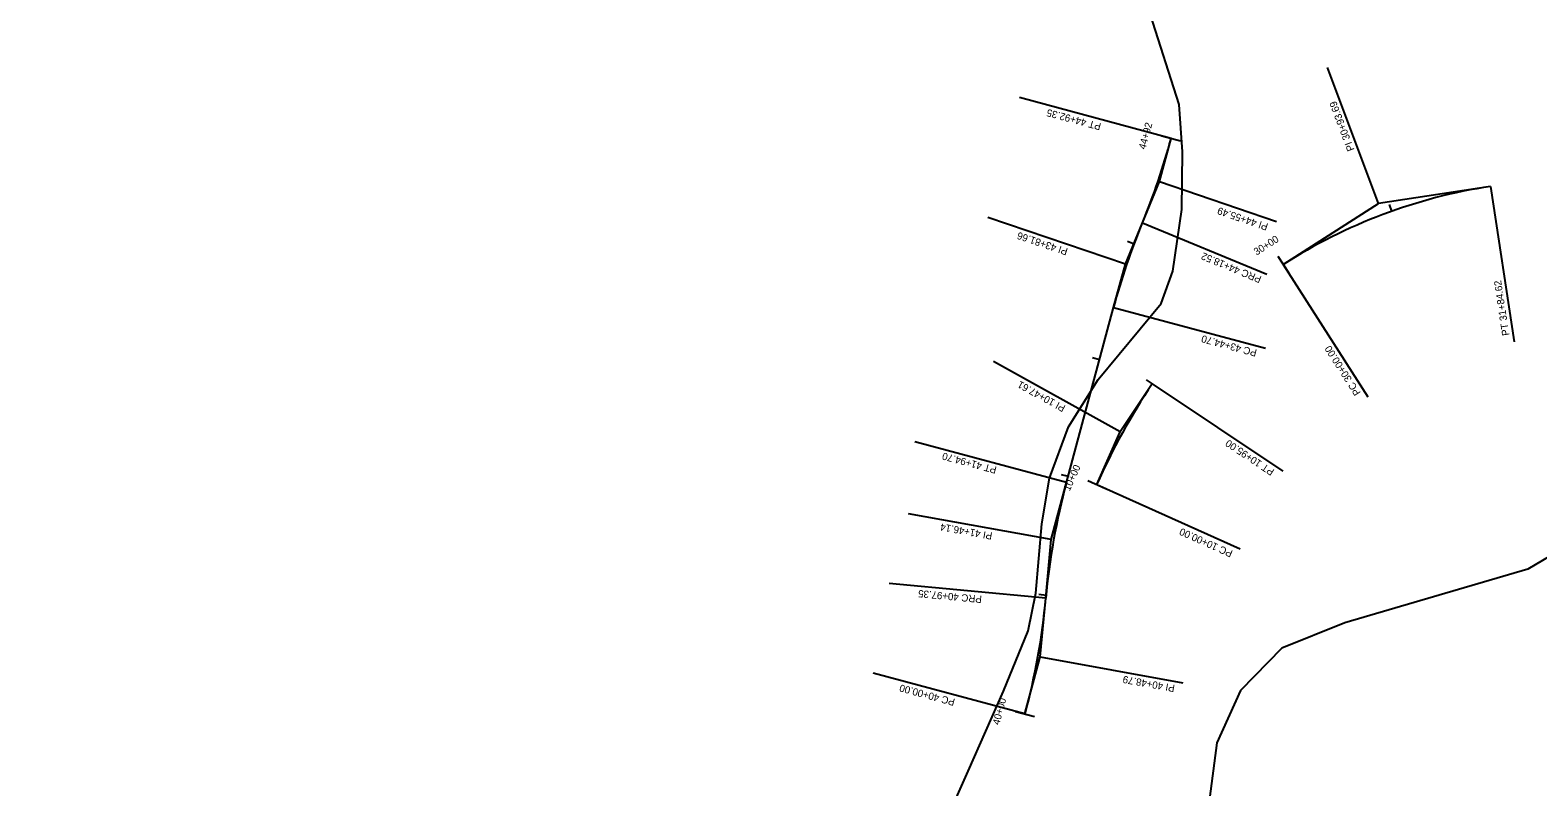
# Model space of a CAD drawing. Extents: x 983486 to 994833, y 1835619 to 1844358.
# Drawn here: x 991785 to 993032, y 1840151 to 1840776 of the extents above; entities that cross this region are included whole.
import ezdxf

# ---------------------------------------------------------------- set-up
doc = ezdxf.new("R2010")
doc.units = 0
for name, color, linetype in [('43', 7, 'Continuous'), ('R_Horz Alg', 7, 'Continuous'), ('R_Horz Alg Annot', 7, 'Continuous'), ('R_Horz Alg Stationing', 7, 'Continuous')]:
    doc.layers.add(name, color=color, linetype=linetype)

msp = doc.modelspace()

# ---------------------------------------------------------------- linework, layer by layer
at = {"layer": '43'}
for points in [[(992621.8, 1840368.1), (992628.1, 1840405.8), (992643.7, 1840448.4), (992668.3, 1840487.4), (992720.4, 1840550.2), (992730.1, 1840577), (992737.5, 1840627.9), (992738, 1840675.6), (992735.4, 1840714.9), (992711.3, 1840789.8), (992657.1, 1840913.4), (992616, 1840968.7), (992554.4, 1841054), (992492.5, 1841112.9), (992422.7, 1841167.6), (992343.9, 1841218.5), (992195, 1841300.3), (992123, 1841334.7), (992016.5, 1841376), (991968.2, 1841403.4), (991911.1, 1841449.2), (991869, 1841500.6), (991810.1, 1841556.1), (991749.1, 1841600.9)], [(992534.5, 1840104.7), (992560.8, 1840163.5), (992590.1, 1840229.7), (992610.3, 1840279.7), (992616.6, 1840310.7), (992621.8, 1840368.1)], [(993078.4, 1840362.9), (993023.9, 1840330.6), (992872.5, 1840286.1), (992820.4, 1840265.3), (992786, 1840230.3), (992766.6, 1840187.1), (992757.7, 1840119.8)]]:
    msp.add_lwpolyline(points, dxfattribs=at)
at = {"layer": 'R_Horz Alg'}
msp.add_line((992642.2, 1840402.3), (992681.1, 1840547.1), dxfattribs=at)
for centre, radius, start, end in [((992175.3, 1840835.7), 573, 337.5525, 344.9354), ((993059.1, 1840211.4), 440.7, 98.6296, 122.6308), ((993234.4, 1840398.2), 573, 157.5525, 164.9354), ((993189.9, 1840166.2), 573, 146.335, 155.835), ((993195.4, 1840253.3), 573, 164.9354, 174.6702), ((992054.5, 1840359.8), 573, 344.9354, 354.6702)]:
    msp.add_arc(centre, radius, start, end, dxfattribs=at)
at = {"layer": 'R_Horz Alg Annot'}
for p, q in [((992719, 1840651.1), (992728.6, 1840686.8)), ((992704.9, 1840617), (992719, 1840651.1)), ((992992.9, 1840647.1), (992900.3, 1840633.1)), ((992821.4, 1840582.6), (992900.3, 1840633.1)), ((992690.8, 1840582.8), (992704.9, 1840617)), ((992681.1, 1840547.1), (992690.8, 1840582.8)), ((992713, 1840483.8), (992686.6, 1840444.1)), ((992667.1, 1840400.7), (992686.6, 1840444.1)), ((992629.5, 1840355.1), (992642.2, 1840402.3)), ((992624.9, 1840306.6), (992629.5, 1840355.1)), ((992620.4, 1840258), (992624.9, 1840306.6)), ((992607.7, 1840210.9), (992620.4, 1840258))]:
    msp.add_line(p, q, dxfattribs=at)
for points in [[(992900.3, 1840633.1), (992858, 1840745.4)], [(992728.6, 1840686.8), (992603.1, 1840720.6)], [(992719, 1840651.1), (992815.9, 1840618.2)], [(992992.9, 1840647.1), (993012.4, 1840518.6)], [(992690.8, 1840582.8), (992577.1, 1840621.4)], [(992704.9, 1840617), (992807.9, 1840574.4)], [(992821.4, 1840582.6), (992891.5, 1840473.1)], [(992681.1, 1840547.1), (992806.7, 1840513.3)], [(992686.6, 1840444.1), (992581.6, 1840502.2)], [(992713, 1840483.8), (992821.2, 1840411.7)], [(992642.2, 1840402.3), (992516.6, 1840436)], [(992667.1, 1840400.7), (992785.7, 1840347.5)], [(992629.5, 1840355.1), (992511.4, 1840376.4)], [(992624.9, 1840306.6), (992495.5, 1840318.6)], [(992620.4, 1840258), (992738.5, 1840236.7)], [(992607.7, 1840210.9), (992482.2, 1840244.7)]]:
    msp.add_lwpolyline(points, dxfattribs=at)
at = {"layer": 'R_Horz Alg Stationing'}
for points in [[(992720.9, 1840688.9), (992736.3, 1840684.7)], [(992720.9, 1840688.9), (992736.3, 1840684.7)], [(992909, 1840632.2), (992911, 1840626.5)], [(992692.5, 1840601.8), (992698.1, 1840599.7)], [(992817.1, 1840589.3), (992825.7, 1840575.8)], [(992663.7, 1840505.5), (992669.5, 1840503.9)], [(992708, 1840487.1), (992713, 1840483.8)], [(992637.7, 1840408.9), (992643.5, 1840407.4)], [(992659.8, 1840404), (992674.4, 1840397.4)], [(992619.2, 1840309.8), (992625.2, 1840309.2)], [(992600, 1840212.9), (992615.5, 1840208.8)]]:
    msp.add_lwpolyline(points, dxfattribs=at)

# ---------------------------------------------------------------- texts
at = {"layer": 'R_Horz Alg Annot'}
for s, rotation, p in [('PI 30+93.69', 110.6302, (992880.4, 1840677.5)), ('PT 44+92.35', 164.9354, (992671.2, 1840699.2)), ('PI 44+55.49', 161.244, (992809.4, 1840616.1)), ('PI 43+81.66', 161.244, (992643.7, 1840595.6)), ('PRC 44+18.52', 157.5525, (992804, 1840572.5)), ('PT 31+84.62', 98.6296, (993008.6, 1840524.1)), ('PC 43+44.70', 164.9354, (992800.1, 1840512)), ('PC 30+00.00', 122.6308, (992885.8, 1840476.5)), ('PI 10+47.61', 151.085, (992641.8, 1840465.5)), ('PT 10+95.00', 146.335, (992814.6, 1840412.5)), ('PT 41+94.70', 164.9354, (992584.8, 1840415.2)), ('PI 41+46.14', 169.8028, (992581.1, 1840360.8)), ('PC 10+00.00', 155.835, (992780.2, 1840345.6)), ('PRC 40+97.35', 174.6702, (992572.3, 1840308.5)), ('PI 40+48.79', 169.8028, (992732.1, 1840234.8)), ('PC 40+00.00', 164.9354, (992550.3, 1840223.2))]:
    msp.add_text(s, height=6, rotation=rotation, dxfattribs=at).set_placement(p)
at = {"layer": 'R_Horz Alg Stationing'}
for s, rotation, p in [('44+92', 74.9354, (992707.4, 1840677.3)), ('44+92', 74.9354, (992707.4, 1840677.3)), ('30+00', 32.6308, (992799.4, 1840589.8)), ('10+00', 65.835, (992644.7, 1840394.7)), ('40+00', 74.9354, (992586.5, 1840201.4))]:
    msp.add_text(s, height=6, rotation=rotation, dxfattribs=at).set_placement(p)

doc.saveas('drawing.dxf')
